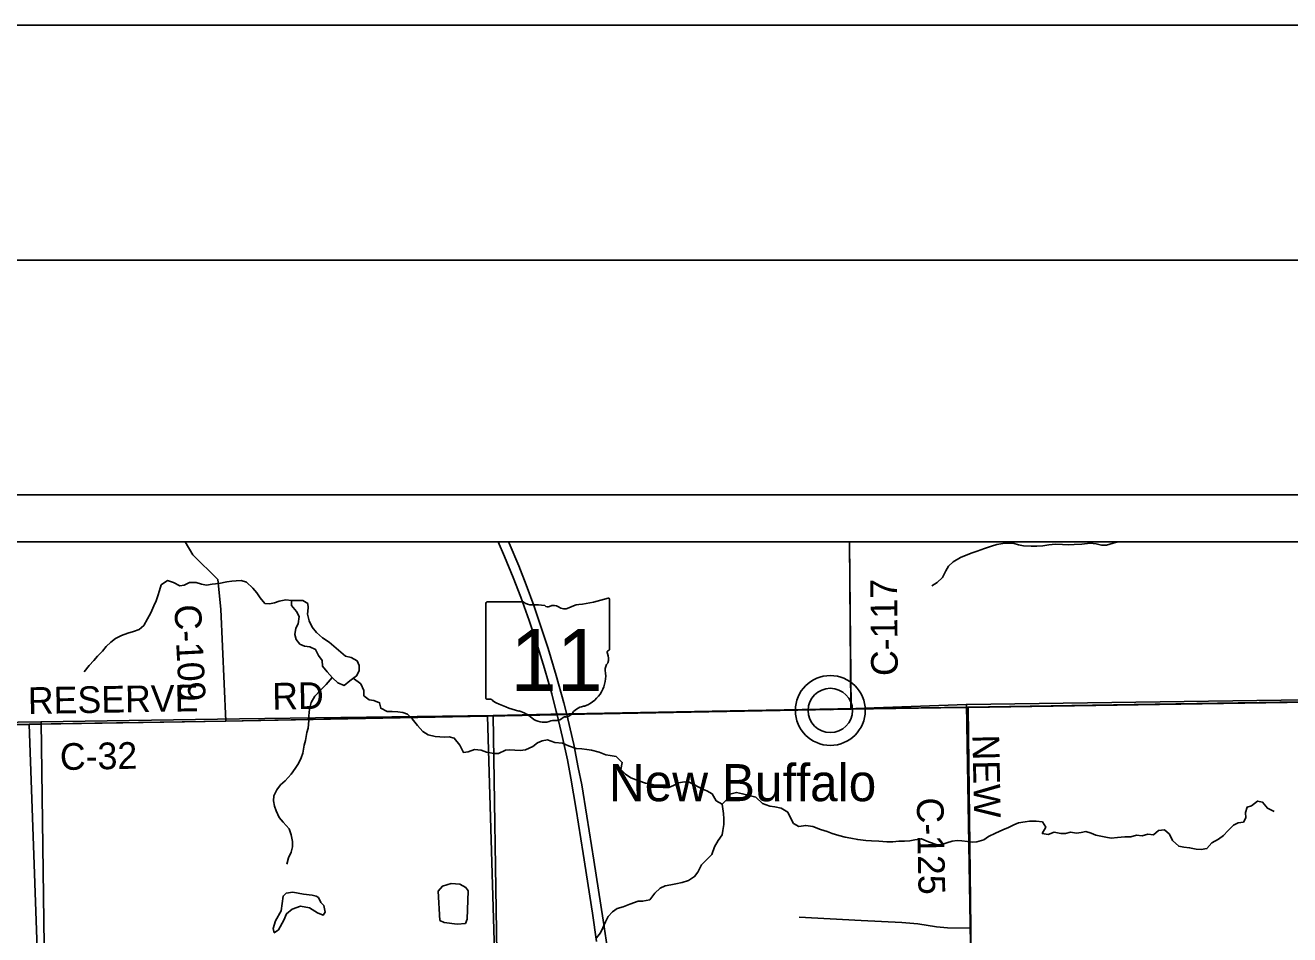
# Model space of a CAD drawing. Extents: x 0 to 36.9, y 0 to 22.
# Drawn here: x 4.166 to 6.858, y 20.063 to 22 of the extents above; entities that cross this region are included whole.
import ezdxf

# ---------------------------------------------------------------- set-up
doc = ezdxf.new("R2010")
doc.units = 0
for name, color, linetype in [('GM_X_County_Road', 7, 'Continuous'), ('GM_X_County_Road_Text', 7, 'Continuous'), ('GM_X_Minor_Lake', 7, 'Continuous'), ('GM_X_Minor_River', 7, 'Continuous'), ('GM_X_Rail_Line', 7, 'Continuous'), ('GM_X_Section', 7, 'Continuous'), ('GM_X_State_Location', 7, 'Continuous'), ('GM_X_State_Route', 7, 'Continuous'), ('GM_X_State_Shield', 7, 'Continuous'), ('GM_X_Township_Road', 7, 'Continuous'), ('GM_X_Unincorporated', 7, 'Continuous'), ('GM_X_Unincorporated_Location', 7, 'Continuous'), ('GM_X_Unincorporated_Text', 7, 'Continuous'), ('SH_Border', 7, 'Continuous'), ('SH_Cut_Line', 7, 'Continuous'), ('SH_Data', 7, 'Continuous')]:
    doc.layers.add(name, color=color, linetype=linetype)

msp = doc.modelspace()

# ---------------------------------------------------------------- linework, layer by layer
at = {"layer": 'GM_X_County_Road'}
for p, q in [((5.9238, 20.544), (5.9207, 20.9)), ((5.1803, 19.5234), (5.1498, 20.5289))]:
    msp.add_line(p, q, dxfattribs=at)
for points in [[(4.5931, 20.5178), (4.5821, 20.7568), (4.5757, 20.8201), (4.5227, 20.8725), (4.5065, 20.9)], [(4.1972, 20.5117), (4.5931, 20.5178), (5.1498, 20.5289), (5.298, 20.5319), (5.3188, 20.5323), (5.9238, 20.544), (6.1629, 20.5471)], [(6.1629, 20.5471), (6.1729, 20.5473), (7.1241, 20.5624)], [(6.1729, 20.5473), (6.1788, 20.0773), (6.1787, 20.0516), (6.1801, 19.9585), (6.187, 19.5342)], [(2.1, 20.4796), (2.6056, 20.4892), (3.1944, 20.4947), (3.4357, 20.499), (4.1744, 20.5113), (4.1972, 20.5117)]]:
    msp.add_lwpolyline(points, dxfattribs=at)
at = {"layer": 'GM_X_Minor_Lake'}
for points in [[(4.8126, 20.6861), (4.7983, 20.6958), (4.7856, 20.707), (4.7763, 20.7186), (4.77, 20.7318), (4.7667, 20.7461), (4.768, 20.7591), (4.7675, 20.7686), (4.7564, 20.7752), (4.7423, 20.7754), (4.7324, 20.7752), (4.7326, 20.7646), (4.7434, 20.7518), (4.7486, 20.7413), (4.7465, 20.7257), (4.7421, 20.7161), (4.7397, 20.7024), (4.7429, 20.6922), (4.7506, 20.6821), (4.7602, 20.6781), (4.7717, 20.6763), (4.7839, 20.6709), (4.7902, 20.658), (4.7976, 20.6475), (4.7985, 20.6354), (4.8086, 20.6234), (4.8199, 20.6107), (4.8314, 20.5995), (4.8445, 20.5944), (4.8568, 20.6041), (4.8711, 20.6146), (4.8767, 20.6253), (4.8769, 20.6363), (4.8721, 20.6469), (4.8599, 20.6535), (4.8473, 20.6563)], [(4.8473, 20.6563), (4.8126, 20.6861)], [(5.1085, 20.1571), (5.1035, 20.1642), (5.0912, 20.1708), (5.0726, 20.1721), (5.054, 20.1668), (5.0447, 20.156), (5.0487, 20.0938), (5.0575, 20.0894), (5.0853, 20.0861), (5.1028, 20.0875), (5.1069, 20.0963)], [(4.7352, 20.154), (4.7216, 20.1515), (4.7148, 20.1457), (4.7104, 20.1145), (4.6985, 20.093), (4.6939, 20.0766), (4.6959, 20.0676), (4.7046, 20.0738), (4.716, 20.0945), (4.7219, 20.1079), (4.7343, 20.1179), (4.752, 20.1239), (4.7711, 20.1204), (4.788, 20.1101), (4.8003, 20.105), (4.8043, 20.1111), (4.8018, 20.1255), (4.7949, 20.1322), (4.7898, 20.1428), (4.7851, 20.1457), (4.7764, 20.1475), (4.7581, 20.1498)], [(4.7581, 20.1498), (4.7352, 20.154)], [(5.1069, 20.0963), (5.1085, 20.1571)]]:
    msp.add_lwpolyline(points, dxfattribs=at)
at = {"layer": 'GM_X_Minor_River'}
for points in [[(6.0962, 20.8065), (6.1075, 20.8135), (6.1187, 20.8239), (6.1257, 20.8385), (6.1316, 20.8481), (6.1413, 20.8577), (6.1571, 20.8668), (6.1687, 20.8715), (6.1819, 20.8767), (6.1925, 20.8799), (6.208, 20.8855), (6.2231, 20.8907), (6.2344, 20.8943), (6.2511, 20.8973), (6.2617, 20.8975), (6.2712, 20.8961), (6.2807, 20.8936), (6.2907, 20.8915), (6.307, 20.8907), (6.3195, 20.8905), (6.3321, 20.8915), (6.3449, 20.8933), (6.3593, 20.895), (6.3742, 20.8942), (6.3863, 20.8933), (6.3992, 20.8946), (6.4151, 20.8953), (6.4326, 20.8971), (6.4455, 20.8955), (6.4573, 20.8926), (6.4676, 20.8928), (6.482, 20.8969), (6.4933, 20.9)], [(4.7324, 20.7752), (4.7203, 20.7763), (4.7063, 20.7734), (4.6961, 20.7702), (4.6859, 20.7681), (4.676, 20.7687), (4.6659, 20.7807), (4.6585, 20.7915), (4.65, 20.8016), (4.6368, 20.8139), (4.6258, 20.8175), (4.6147, 20.8173), (4.6053, 20.8164), (4.5947, 20.8147), (4.5776, 20.8114), (4.564, 20.8096), (4.5515, 20.8079), (4.5412, 20.8096), (4.5294, 20.8132), (4.5157, 20.8133), (4.5044, 20.8078), (4.4946, 20.8061), (4.4815, 20.8131), (4.4689, 20.8174), (4.455, 20.8081), (4.4515, 20.7966), (4.4482, 20.7852), (4.4443, 20.7741), (4.4395, 20.7634), (4.4329, 20.7488), (4.4263, 20.7358), (4.4182, 20.722), (4.4085, 20.7135), (4.3964, 20.7091), (4.384, 20.7054), (4.3708, 20.7003), (4.358, 20.694), (4.3479, 20.6866), (4.3382, 20.6769), (4.33, 20.6673), (4.3195, 20.6568), (4.3117, 20.6472), (4.302, 20.6368), (4.2913, 20.6229)], [(4.8195, 20.611), (4.8066, 20.5964), (4.7951, 20.5848), (4.782, 20.5717), (4.7743, 20.5579), (4.7711, 20.5438), (4.7695, 20.5293), (4.7693, 20.5198), (4.768, 20.5035), (4.7656, 20.4939), (4.7621, 20.4768), (4.7596, 20.4669), (4.7568, 20.4501), (4.7529, 20.4398), (4.7474, 20.4283), (4.7403, 20.4172), (4.7322, 20.4049), (4.7188, 20.391), (4.7091, 20.3825), (4.7017, 20.3721), (4.6947, 20.3591), (4.6941, 20.3488), (4.6966, 20.3371), (4.7002, 20.3273), (4.7065, 20.3133), (4.715, 20.3029), (4.7278, 20.2887), (4.7322, 20.2758), (4.7351, 20.2618), (4.7346, 20.2508), (4.7321, 20.239), (4.7259, 20.2268), (4.7227, 20.2134)], [(4.8641, 20.6094), (4.8799, 20.5977), (4.8866, 20.5834), (4.8864, 20.5724), (4.898, 20.5635), (4.9079, 20.5621), (4.9201, 20.5574), (4.9226, 20.5457), (4.9364, 20.5387), (4.947, 20.5385), (4.9592, 20.538), (4.9699, 20.5363), (4.9798, 20.533), (4.9898, 20.5234), (5.0007, 20.5087), (5.012, 20.4964), (5.0239, 20.489), (5.0384, 20.4855), (5.0482, 20.4845), (5.0585, 20.4843), (5.0684, 20.4845), (5.079, 20.4817), (5.0907, 20.4671), (5.0986, 20.4516), (5.1088, 20.4526), (5.1224, 20.4578), (5.1365, 20.4561), (5.1479, 20.4518), (5.1639, 20.449), (5.1734, 20.4496), (5.1881, 20.4563), (5.1976, 20.4572), (5.2078, 20.4562), (5.2196, 20.4553), (5.2306, 20.457), (5.2464, 20.4641), (5.2562, 20.4719), (5.266, 20.4763), (5.2777, 20.4784), (5.2934, 20.4729), (5.3093, 20.4713), (5.322, 20.4659), (5.3388, 20.4601), (5.3506, 20.4592), (5.3616, 20.4575), (5.3711, 20.4561), (5.3875, 20.4518), (5.4017, 20.4464), (5.4112, 20.445), (5.4238, 20.443), (5.4369, 20.4303), (5.4334, 20.4151), (5.4434, 20.405), (5.4553, 20.3976), (5.4722, 20.3911), (5.4863, 20.3864), (5.4981, 20.3836), (5.5107, 20.3804), (5.5244, 20.3765), (5.5362, 20.3767), (5.546, 20.381), (5.5562, 20.3865), (5.569, 20.3886), (5.5793, 20.3881), (5.5908, 20.3826), (5.6061, 20.3737), (5.6168, 20.3701), (5.628, 20.3631), (5.6366, 20.3485), (5.6496, 20.3415), (5.6593, 20.3511), (5.6659, 20.363), (5.6803, 20.3663), (5.6925, 20.3635), (5.7101, 20.3589), (5.7211, 20.356), (5.7354, 20.343), (5.7507, 20.3372), (5.7614, 20.3355), (5.7751, 20.3331), (5.7893, 20.3242), (5.796, 20.3111), (5.8015, 20.3005), (5.8126, 20.2935), (5.8274, 20.296), (5.8426, 20.2937), (5.859, 20.2875), (5.8732, 20.2828), (5.8835, 20.2788), (5.8976, 20.2749), (5.911, 20.2713), (5.9235, 20.2689), (5.938, 20.2661), (5.9555, 20.2642), (5.9677, 20.2632), (5.9829, 20.2624), (6, 20.2612), (6.0125, 20.2614), (6.0258, 20.2624), (6.038, 20.2626), (6.0493, 20.2636)], [(5.6496, 20.3415), (5.6526, 20.3218), (5.6528, 20.31), (5.6527, 20.2983), (5.6506, 20.2853), (5.6493, 20.2758), (5.6411, 20.2639), (5.6334, 20.2508), (5.6272, 20.2344), (5.6056, 20.212), (5.5975, 20.1967), (5.5908, 20.1871), (5.5781, 20.1785), (5.5645, 20.1748), (5.5505, 20.1716), (5.5403, 20.1699), (5.5282, 20.1677), (5.5172, 20.1626), (5.506, 20.1518), (5.4953, 20.1379), (5.4801, 20.1346), (5.4703, 20.1348), (5.4529, 20.1281), (5.439, 20.1229), (5.4257, 20.1192), (5.416, 20.1122), (5.4071, 20.1022), (5.4012, 20.0907), (5.3957, 20.0781), (5.3902, 20.0674), (5.382, 20.0566)], [(6.0493, 20.2636), (6.0595, 20.2653), (6.0736, 20.2678), (6.0885, 20.2612), (6.1072, 20.2547), (6.1167, 20.2553), (6.1276, 20.2593), (6.1393, 20.2625), (6.1496, 20.2638), (6.1595, 20.2632), (6.172, 20.2616), (6.1819, 20.2606), (6.1918, 20.2608), (6.2069, 20.2656), (6.2166, 20.2722), (6.2313, 20.2797), (6.2471, 20.2865), (6.2592, 20.2916), (6.2705, 20.2975), (6.2807, 20.3019), (6.2943, 20.304), (6.3041, 20.3049), (6.3182, 20.3052), (6.3311, 20.3035), (6.3382, 20.2923), (6.3308, 20.2792), (6.3438, 20.2768), (6.3562, 20.2816), (6.3703, 20.2792), (6.3806, 20.2786), (6.3911, 20.2818), (6.4041, 20.2798), (6.4136, 20.2807), (6.4234, 20.2828), (6.4352, 20.2796), (6.4452, 20.2752), (6.4559, 20.2731), (6.4661, 20.2714), (6.4779, 20.2693), (6.4912, 20.2703), (6.5068, 20.2718), (6.5197, 20.272), (6.5318, 20.2756), (6.5436, 20.2739), (6.5556, 20.2776), (6.5678, 20.2763), (6.5787, 20.2852), (6.5912, 20.2869), (6.6016, 20.2773), (6.6079, 20.2641), (6.6214, 20.2518), (6.6321, 20.2501), (6.6446, 20.2484), (6.6588, 20.2453), (6.669, 20.2447), (6.6815, 20.2468), (6.6916, 20.2588), (6.7062, 20.2666), (6.7167, 20.2748), (6.726, 20.2845), (6.738, 20.2964), (6.7481, 20.3019), (6.7591, 20.3029), (6.7646, 20.3125), (6.7637, 20.3235), (6.7669, 20.3349), (6.7767, 20.3381), (6.7895, 20.3479), (6.8001, 20.3454), (6.8102, 20.3327), (6.8244, 20.3254)]]:
    msp.add_lwpolyline(points, dxfattribs=at)
at = {"layer": 'GM_X_Rail_Line'}
for points in [[(5.9205, 20.9), (2.1, 20.9), (2.1, 20.4802), (2.6054, 20.4898), (3.1942, 20.4953), (3.4355, 20.4995), (4.1742, 20.5119), (4.5929, 20.5183), (5.1496, 20.5295), (5.2978, 20.5324), (5.3186, 20.5329), (5.9236, 20.5446)], [(8.9, 20.5927), (8.9, 20.9), (5.9205, 20.9), (5.9236, 20.5446), (6.1727, 20.5478), (7.1468, 20.5633), (7.1656, 20.5637), (7.4889, 20.5693), (7.7514, 20.5725), (8.1451, 20.581), (8.4706, 20.5777), (8.4791, 20.5781), (8.7004, 20.5894)]]:
    msp.add_lwpolyline(points, close=True, dxfattribs=at)
for points in [[(8.9, 14.5158), (8.9, 20.5927), (8.7004, 20.5894), (8.4791, 20.5781), (8.4706, 20.5777), (8.1451, 20.581), (7.7514, 20.5725), (7.4889, 20.5693), (7.1656, 20.5637), (7.1468, 20.5633), (6.1727, 20.5478), (5.9236, 20.5446), (5.3186, 20.5329), (5.2978, 20.5324), (5.1496, 20.5295), (4.5929, 20.5183), (4.1742, 20.5119), (4.2095, 19.5156), (4.2124, 19.4314), (4.22, 18.531), (4.2174, 18.4382), (4.2214, 17.442), (4.2237, 16.806), (4.2428, 16.065)], [(4.2428, 16.065), (4.2237, 16.806), (4.2214, 17.442), (4.2174, 18.4382), (4.22, 18.531), (4.2124, 19.4314), (4.2095, 19.5156), (4.1742, 20.5119), (3.4355, 20.4995), (3.1942, 20.4953), (2.6054, 20.4898), (2.1, 20.4802), (2.1, 14.4405)]]:
    msp.add_lwpolyline(points, dxfattribs=at)
at = {"layer": 'GM_X_Section'}
for points in [[(7.1483, 20.5676), (7.1591, 19.5574), (6.1867, 19.5319), (6.1696, 20.5537), (6.9427, 20.5639)], [(6.1696, 20.5537), (6.1867, 19.5319), (5.1777, 19.5195), (5.1623, 20.5304), (5.285, 20.533), (5.9343, 20.5451)], [(4.1996, 20.5167), (4.2133, 19.5112), (4.212, 19.4289), (3.2188, 19.419), (3.2025, 20.497), (3.3829, 20.4998), (3.9553, 20.5131)], [(5.1623, 20.5304), (5.1777, 19.5195), (4.2133, 19.5112), (4.1996, 20.5167), (4.6217, 20.5229)]]:
    msp.add_lwpolyline(points, close=True, dxfattribs=at)
at = {"layer": 'GM_X_State_Route'}
for points in [[(5.3823, 20.049), (5.3732, 20.1089), (5.3533, 20.2366), (5.3389, 20.3297), (5.3273, 20.3965), (5.3203, 20.4356), (5.3097, 20.4836), (5.298, 20.5319), (5.2964, 20.5386), (5.2865, 20.5761), (5.2712, 20.63), (5.254, 20.6858), (5.2383, 20.7322), (5.2207, 20.7819), (5.2043, 20.8241), (5.186, 20.8686), (5.1727, 20.9)], [(5.4047, 20.0375), (5.3958, 20.0944), (5.3762, 20.2221), (5.3616, 20.3155), (5.3505, 20.3823), (5.3431, 20.4195), (5.3336, 20.4687), (5.3209, 20.5233), (5.3188, 20.5323), (5.3125, 20.5568), (5.2964, 20.6157), (5.2793, 20.6725), (5.2652, 20.7156), (5.2484, 20.7646), (5.2324, 20.8085), (5.2163, 20.8487), (5.1961, 20.8969), (5.1947, 20.9)]]:
    msp.add_lwpolyline(points, dxfattribs=at)
at = {"layer": 'GM_X_State_Shield'}
for p, q in [((5.1462, 20.7685), (5.1462, 20.5684)), ((5.226, 20.772), (5.1488, 20.772)), ((5.4099, 20.6722), (5.4099, 20.7769)), ((5.4098, 20.6723), (5.4099, 20.6722))]:
    msp.add_line(p, q, dxfattribs=at)
for centre, radius, start, end in [((5.1492, 20.7689), 0.00305, 98.1301, 188.1301), ((5.2444, 20.7952), 0.0296, 231.6195, 271.1119), ((5.2542, 20.6596), 0.1064, 80.4867, 94.9883), ((5.2784, 20.77), 0.00855, 219.7921, 297.1024), ((5.2909, 20.7468), 0.0178, 54.4667, 119.1411), ((5.3139, 20.7786), 0.0214, 233.8562, 294.8282), ((5.3516, 20.7108), 0.0563, 97.3462, 120.7689), ((5.3159, 21.0448), 0.2796, 275.8445, 288.9065), ((5.4069, 20.7773), 0.00294, 351.8621, 97.738), ((5.4092, 20.6645), 0.00454, 107.944, 210.337), ((5.3803, 20.6513), 0.0273, 340.033, 23.6496), ((5.4067, 20.6718), 0.00314, 289.6038, 7.7341), ((5.3316, 20.6151), 0.0699, 292.3089, 8.9858), ((5.4204, 20.6284), 0.0198, 136.8065, 186.9296), ((5.1492, 20.568), 0.00308, 171.9584, 258.3066), ((5.1497, 20.5884), 0.0235, 267.339, 280.6039), ((5.1545, 20.5568), 0.00848, 29.7484, 93.2717), ((5.2616, 20.7366), 0.2019, 240.4129, 257.1985), ((5.2014, 20.4785), 0.0632, 47.1842, 75.836), ((5.3611, 20.5122), 0.0383, 94.4031, 142.5768), ((5.2697, 20.5559), 0.0401, 230.7004, 286.2918), ((5.2929, 20.4867), 0.0329, 85.6951, 111.2099), ((5.2958, 20.5409), 0.0214, 268.777, 315.5493), ((5.3151, 20.5215), 0.00601, 65.7517, 132.6484), ((5.3126, 20.549), 0.0226, 282.8732, 323.2771)]:
    msp.add_arc(centre, radius, start, end, dxfattribs=at)
at = {"layer": 'GM_X_Township_Road'}
msp.add_lwpolyline([(5.8132, 20.1006), (5.9457, 20.0933), (6.0322, 20.0893), (6.0657, 20.0862), (6.1055, 20.0803), (6.1293, 20.0782), (6.1788, 20.0773)], dxfattribs=at)
at = {"layer": 'GM_X_Unincorporated'}
for radius in [0.0744, 0.0472]:
    msp.add_circle((5.8797, 20.5409), radius, dxfattribs=at)
at = {"layer": 'GM_X_Unincorporated_Location'}
msp.add_line((5.8797, 20.5409), (5.8797, 20.5409), dxfattribs=at)
at = {"layer": 'SH_Border'}
msp.add_lwpolyline([(1.5, 21.5), (33.5, 21.5), (33.5, 0.5), (1.5, 0.5)], close=True, dxfattribs=at)
at = {"layer": 'SH_Cut_Line'}
msp.add_lwpolyline([(0, 0), (34, 0), (34, 22), (0, 22)], close=True, dxfattribs=at)
msp.add_lwpolyline([(8.9, 14.5158), (8.9, 20.9), (2.1, 20.9), (2.1, 14.4405)], dxfattribs=at)
at = {"layer": 'SH_Data'}
for p, q in [((2, 21), (9, 21)), ((2.1, 20.9), (8.9, 20.9))]:
    msp.add_line(p, q, dxfattribs=at)

# ---------------------------------------------------------------- texts
at = {"layer": 'GM_X_County_Road_Text'}
for s, rotation, p in [('C-117', 90.5506, (6.0236, 20.6145)), ('C-109', 272.9151, (4.483, 20.7654)), ('RESERVE', 0.9304, (4.1718, 20.5334)), ('RD', 0.9977, (4.692, 20.5426)), ('C-32', 1.0286, (4.24, 20.414)), ('NEW', 271.2065, (6.1822, 20.4891)), ('C-125', 271.1022, (6.0637, 20.355))]:
    msp.add_text(s, height=0.05682, rotation=rotation, dxfattribs=at).set_placement(p)
at = {"layer": 'GM_X_State_Location'}
for s, p in [('s', (5.2751, 20.6551)), ('r', (5.275, 20.6551))]:
    msp.add_text(s, height=0.000189, dxfattribs=at).set_placement(p)
msp.add_text('11', height=0.000189, rotation=0, dxfattribs=at).set_placement((5.2274, 20.6414))
at = {"layer": 'GM_X_State_Shield'}
msp.add_text('11', height=0.13184, dxfattribs=at).set_placement((5.1989, 20.5825))
at = {"layer": 'GM_X_Unincorporated_Text'}
msp.add_text('New Buffalo', height=0.078977, rotation=0, dxfattribs=at).set_placement((5.4082, 20.3477))

doc.saveas('drawing.dxf')
